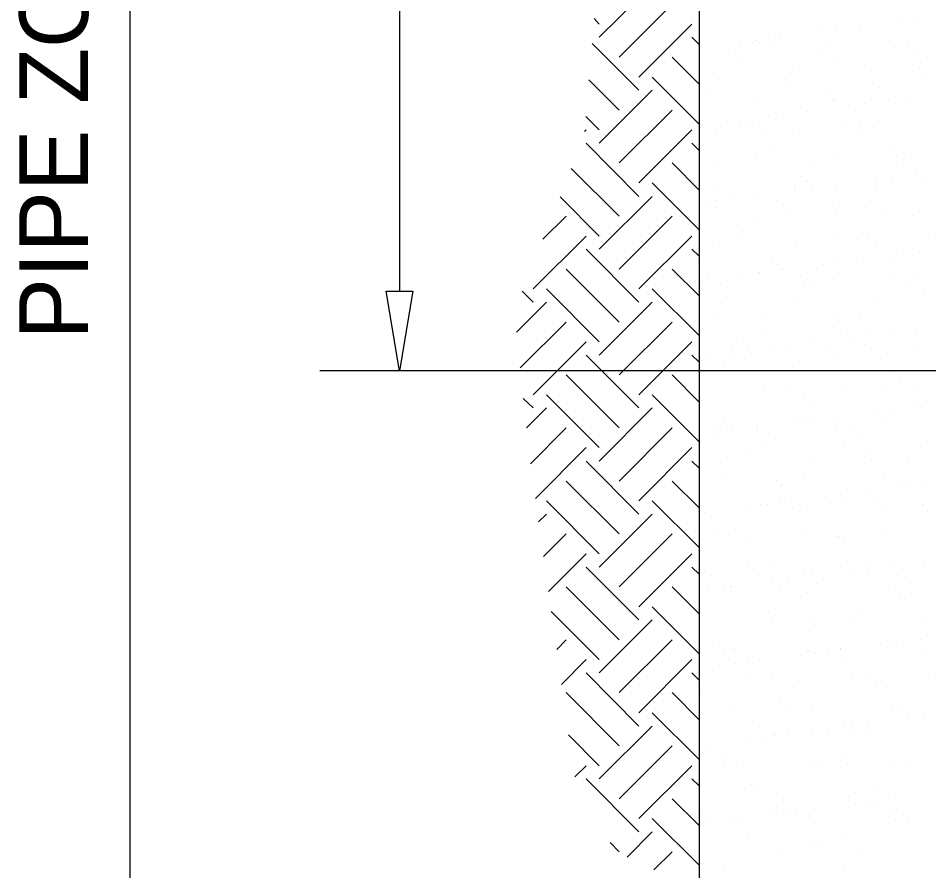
# Model space of a CAD drawing. Extents: x -118779 to -116979, y -104389 to -102939.
# Drawn here: x -117656.9 to -117577.5, y -103296.4 to -103222.1 of the extents above; entities that cross this region are included whole.
import ezdxf

# ---------------------------------------------------------------- set-up
doc = ezdxf.new("R2010")
doc.units = 0
for name, color, linetype in [('G-MARK', 7, 'Continuous'), ('G-TEXT', 7, 'Continuous'), ('Misc CnstDet(22)', 7, 'Continuous')]:
    doc.layers.add(name, color=color, linetype=linetype)

msp = doc.modelspace()

# ---------------------------------------------------------------- linework, layer by layer
at = {"layer": 'G-MARK'}
for p, q in [((-117647.13, -103155.313), (-117647.13, -103305.517)), ((-117623.616, -103155.313), (-117623.616, -103245.874)), ((-117512.18, -103252.832), (-117630.574, -103252.832))]:
    msp.add_line(p, q, dxfattribs=at)
at = {"layer": 'G-TEXT'}
msp.add_lwpolyline([(-117624.781, -103245.874), (-117622.45, -103245.874), (-117623.616, -103252.832)], close=True, dxfattribs=at)
at = {"layer": 'Misc CnstDet(22)'}
for p, q in [((-117597.496, -103148.355), (-117597.496, -103341.508)), ((-117606.203, -103223.731), (-117601.575, -103219.138)), ((-117604.455, -103225.479), (-117599.827, -103220.851)), ((-117606.203, -103222.6), (-117606.648, -103222.12)), ((-117579.809, -103222.325), (-117579.809, -103222.325)), ((-117578.472, -103222.154), (-117578.472, -103222.154)), ((-117602.741, -103227.227), (-117598.113, -103222.6)), ((-117586.836, -103223.251), (-117586.836, -103223.251)), ((-117585.499, -103223.08), (-117585.499, -103223.08)), ((-117583.374, -103222.805), (-117583.374, -103222.805)), ((-117597.496, -103224.382), (-117598.113, -103223.731)), ((-117592.526, -103224.005), (-117592.526, -103224.005)), ((-117591.463, -103223.799), (-117591.463, -103223.799)), ((-117590.401, -103223.731), (-117590.401, -103223.731)), ((-117586.013, -103224.142), (-117586.013, -103224.142)), ((-117580.872, -103224.005), (-117580.872, -103224.005)), ((-117602.741, -103228.358), (-117606.82, -103224.279)), ((-117597.428, -103224.656), (-117597.428, -103224.656)), ((-117594.96, -103224.896), (-117594.96, -103224.896)), ((-117593.897, -103224.176), (-117593.897, -103224.176)), ((-117592.835, -103224.245), (-117592.835, -103224.245)), ((-117590.984, -103224.245), (-117590.984, -103224.245)), ((-117586.802, -103224.862), (-117586.802, -103224.862)), ((-117579.329, -103224.176), (-117579.329, -103224.176)), ((-117578.678, -103224.862), (-117578.678, -103224.862)), ((-117597.496, -103227.844), (-117599.827, -103225.479)), ((-117593.829, -103225.582), (-117593.829, -103225.582)), ((-117585.705, -103225.582), (-117585.705, -103225.582)), ((-117577.581, -103225.547), (-117577.581, -103225.547)), ((-117588.721, -103226.302), (-117588.721, -103226.302)), ((-117578.267, -103226.404), (-117578.267, -103226.404)), ((-117597.496, -103231.306), (-117601.575, -103227.227)), ((-117596.228, -103226.816), (-117596.228, -103226.816)), ((-117589.544, -103226.85), (-117589.544, -103226.85)), ((-117582.483, -103226.61), (-117582.483, -103226.61)), ((-117577.787, -103226.85), (-117577.787, -103226.85)), ((-117604.455, -103230.106), (-117607.094, -103227.467)), ((-117581.729, -103228.084), (-117581.729, -103228.084)), ((-117606.203, -103232.986), (-117601.575, -103228.358)), ((-117596.571, -103228.598), (-117596.571, -103228.598)), ((-117589.887, -103228.118), (-117589.887, -103228.118)), ((-117586.116, -103228.701), (-117586.116, -103228.701)), ((-117592.697, -103229.249), (-117592.697, -103229.249)), ((-117585.842, -103229.181), (-117585.842, -103229.181)), ((-117585.636, -103229.147), (-117585.636, -103229.147)), ((-117584.437, -103229.695), (-117584.437, -103229.695)), ((-117583.1, -103229.524), (-117583.1, -103229.524)), ((-117580.975, -103229.249), (-117580.975, -103229.249)), ((-117579.158, -103229.215), (-117579.158, -103229.215)), ((-117604.455, -103234.7), (-117599.827, -103230.106)), ((-117590.127, -103230.449), (-117590.127, -103230.449)), ((-117588.001, -103230.175), (-117588.001, -103230.175)), ((-117606.203, -103231.82), (-117607.368, -103230.655)), ((-117595.028, -103231.1), (-117595.028, -103231.1)), ((-117593.966, -103230.998), (-117593.966, -103230.998)), ((-117591.463, -103230.621), (-117591.463, -103230.621)), ((-117583.374, -103231.203), (-117583.374, -103231.203)), ((-117607.471, -103231.957), (-117607.334, -103231.82)), ((-117602.741, -103236.448), (-117598.113, -103231.82)), ((-117597.153, -103231.375), (-117597.153, -103231.375)), ((-117596.057, -103231.855), (-117596.057, -103231.855)), ((-117593.486, -103231.443), (-117593.486, -103231.443)), ((-117592.835, -103231.409), (-117592.835, -103231.409)), ((-117589.372, -103231.889), (-117589.372, -103231.889)), ((-117584.711, -103231.409), (-117584.711, -103231.409)), ((-117582.311, -103231.615), (-117582.311, -103231.615)), ((-117591.738, -103232.129), (-117591.738, -103232.129)), ((-117583.614, -103232.129), (-117583.614, -103232.129)), ((-117602.741, -103237.613), (-117607.334, -103232.986)), ((-117597.496, -103233.603), (-117598.113, -103232.986)), ((-117591.223, -103233.5), (-117591.223, -103233.5)), ((-117580.769, -103233.603), (-117580.769, -103233.603)), ((-117592.526, -103234.288), (-117592.526, -103234.288)), ((-117585.671, -103234.22), (-117585.671, -103234.22)), ((-117580.289, -103234.048), (-117580.289, -103234.048)), ((-117578.986, -103234.254), (-117578.986, -103234.254)), ((-117604.455, -103239.327), (-117608.636, -103235.179)), ((-117597.496, -103237.065), (-117599.827, -103234.7)), ((-117595.919, -103234.665), (-117595.919, -103234.665)), ((-117587.761, -103234.665), (-117587.761, -103234.665)), ((-117579.638, -103234.631), (-117579.638, -103234.631)), ((-117588.618, -103235.899), (-117588.618, -103235.899)), ((-117580.666, -103235.968), (-117580.666, -103235.968)), ((-117578.541, -103235.694), (-117578.541, -103235.694)), ((-117597.496, -103240.527), (-117601.575, -103236.448)), ((-117588.139, -103236.345), (-117588.139, -103236.345)), ((-117585.568, -103236.619), (-117585.568, -103236.619)), ((-117582.14, -103236.653), (-117582.14, -103236.653)), ((-117582.037, -103236.139), (-117582.037, -103236.139)), ((-117578.027, -103236.105), (-117578.027, -103236.105)), ((-117606.203, -103242.206), (-117601.575, -103237.613)), ((-117595.885, -103236.893), (-117595.885, -103236.893)), ((-117592.629, -103237.545), (-117592.629, -103237.545)), ((-117589.201, -103236.928), (-117589.201, -103236.928)), ((-117589.064, -103237.065), (-117589.064, -103237.065)), ((-117587.693, -103236.893), (-117587.693, -103236.893)), ((-117606.203, -103241.075), (-117609.596, -103237.647)), ((-117596.468, -103238.196), (-117596.468, -103238.196)), ((-117596.091, -103237.99), (-117596.091, -103237.99)), ((-117594.754, -103237.819), (-117594.754, -103237.819)), ((-117590.709, -103237.956), (-117590.709, -103237.956)), ((-117585.876, -103238.402), (-117585.876, -103238.402)), ((-117582.586, -103237.956), (-117582.586, -103237.956)), ((-117595.988, -103238.607), (-117595.988, -103238.607)), ((-117589.612, -103238.676), (-117589.612, -103238.676)), ((-117581.489, -103238.641), (-117581.489, -103238.641)), ((-117611.104, -103241.349), (-117609.082, -103239.327)), ((-117604.455, -103243.954), (-117599.827, -103239.327)), ((-117592.355, -103239.327), (-117592.355, -103239.327)), ((-117585.533, -103239.258), (-117585.533, -103239.258)), ((-117578.849, -103239.258), (-117578.849, -103239.258)), ((-117593.726, -103240.698), (-117593.726, -103240.698)), ((-117583.271, -103240.801), (-117583.271, -103240.801)), ((-117611.961, -103245.668), (-117607.334, -103241.075)), ((-117602.741, -103245.668), (-117598.113, -103241.075)), ((-117593.794, -103241.212), (-117593.794, -103241.212)), ((-117585.671, -103241.178), (-117585.671, -103241.178)), ((-117582.791, -103241.247), (-117582.791, -103241.247)), ((-117577.513, -103241.178), (-117577.513, -103241.178)), ((-117602.741, -103246.834), (-117607.334, -103242.206)), ((-117597.496, -103242.823), (-117598.113, -103242.206)), ((-117595.714, -103241.898), (-117595.714, -103241.898)), ((-117589.03, -103241.932), (-117589.03, -103241.932)), ((-117582.003, -103241.692), (-117582.003, -103241.692)), ((-117591.121, -103243.098), (-117591.121, -103243.098)), ((-117583.168, -103243.063), (-117583.168, -103243.063)), ((-117579.638, -103242.583), (-117579.638, -103242.583)), ((-117578.267, -103242.412), (-117578.267, -103242.412)), ((-117604.455, -103248.582), (-117609.082, -103243.954)), ((-117597.496, -103246.285), (-117599.827, -103243.954)), ((-117590.641, -103243.543), (-117590.641, -103243.543)), ((-117590.195, -103243.989), (-117590.195, -103243.989)), ((-117586.665, -103243.509), (-117586.665, -103243.509)), ((-117585.293, -103243.337), (-117585.293, -103243.337)), ((-117580.529, -103243.303), (-117580.529, -103243.303)), ((-117596.742, -103244.537), (-117596.742, -103244.537)), ((-117593.691, -103244.434), (-117593.691, -103244.434)), ((-117592.32, -103244.263), (-117592.32, -103244.263)), ((-117592.183, -103244.366), (-117592.183, -103244.366)), ((-117588.618, -103244.503), (-117588.618, -103244.503)), ((-117585.362, -103244.263), (-117585.362, -103244.263)), ((-117580.495, -103244.503), (-117580.495, -103244.503)), ((-117578.678, -103244.297), (-117578.678, -103244.297)), ((-117597.222, -103244.914), (-117597.222, -103244.914)), ((-117595.645, -103245.223), (-117595.645, -103245.223)), ((-117587.522, -103245.223), (-117587.522, -103245.223)), ((-117579.398, -103245.188), (-117579.398, -103245.188)), ((-117611.961, -103246.834), (-117612.921, -103245.874)), ((-117606.203, -103250.296), (-117610.796, -103245.668)), ((-117597.496, -103249.747), (-117601.575, -103245.668)), ((-117588.378, -103245.6), (-117588.378, -103245.6)), ((-117577.924, -103245.703), (-117577.924, -103245.703)), ((-117613.401, -103249.439), (-117610.796, -103246.834)), ((-117606.203, -103251.461), (-117601.575, -103246.834)), ((-117595.577, -103246.937), (-117595.577, -103246.937)), ((-117588.893, -103246.971), (-117588.893, -103246.971)), ((-117581.831, -103246.731), (-117581.831, -103246.731)), ((-117596.228, -103247.896), (-117596.228, -103247.896)), ((-117591.669, -103247.759), (-117591.669, -103247.759)), ((-117583.545, -103247.725), (-117583.545, -103247.725)), ((-117613.092, -103252.558), (-117609.082, -103248.582)), ((-117604.455, -103253.175), (-117599.827, -103248.582)), ((-117585.773, -103247.999), (-117585.773, -103247.999)), ((-117585.293, -103248.445), (-117585.293, -103248.445)), ((-117592.012, -103249.405), (-117592.012, -103249.405)), ((-117585.191, -103249.302), (-117585.191, -103249.302)), ((-117580.769, -103249.507), (-117580.769, -103249.507)), ((-117578.507, -103249.336), (-117578.507, -103249.336)), ((-117611.961, -103254.923), (-117607.334, -103250.296)), ((-117602.741, -103254.923), (-117598.113, -103250.296)), ((-117593.623, -103250.296), (-117593.623, -103250.296)), ((-117584.265, -103249.953), (-117584.265, -103249.953)), ((-117582.894, -103249.782), (-117582.894, -103249.782)), ((-117594.651, -103251.05), (-117594.651, -103251.05)), ((-117593.143, -103250.741), (-117593.143, -103250.741)), ((-117591.292, -103250.879), (-117591.292, -103250.879)), ((-117589.921, -103250.707), (-117589.921, -103250.707)), ((-117587.796, -103250.433), (-117587.796, -103250.433)), ((-117586.493, -103251.05), (-117586.493, -103251.05)), ((-117583.031, -103250.501), (-117583.031, -103250.501)), ((-117578.369, -103251.016), (-117578.369, -103251.016)), ((-117602.741, -103256.054), (-117607.334, -103251.461)), ((-117597.496, -103252.078), (-117598.113, -103251.461)), ((-117596.948, -103251.633), (-117596.948, -103251.633)), ((-117594.823, -103251.358), (-117594.823, -103251.358)), ((-117593.554, -103251.77), (-117593.554, -103251.77)), ((-117585.396, -103251.735), (-117585.396, -103251.735)), ((-117581.66, -103251.77), (-117581.66, -103251.77)), ((-117595.405, -103251.975), (-117595.405, -103251.975)), ((-117588.721, -103252.01), (-117588.721, -103252.01)), ((-117623.616, -103252.832), (-117623.616, -103252.832)), ((-117604.455, -103257.803), (-117609.082, -103253.175)), ((-117597.496, -103255.54), (-117599.827, -103253.175)), ((-117590.881, -103252.798), (-117590.881, -103252.798)), ((-117580.426, -103252.901), (-117580.426, -103252.901)), ((-117579.946, -103253.346), (-117579.946, -103253.346)), ((-117589.578, -103254.306), (-117589.578, -103254.306)), ((-117581.454, -103254.272), (-117581.454, -103254.272)), ((-117606.203, -103259.516), (-117610.796, -103254.923)), ((-117597.496, -103259.002), (-117601.575, -103254.923)), ((-117591.875, -103254.443), (-117591.875, -103254.443)), ((-117585.019, -103254.341), (-117585.019, -103254.341)), ((-117578.335, -103254.375), (-117578.335, -103254.375)), ((-117611.961, -103256.054), (-117612.818, -103255.232)), ((-117588.276, -103255.197), (-117588.276, -103255.197)), ((-117587.796, -103255.643), (-117587.796, -103255.643)), ((-117577.65, -103255.437), (-117577.65, -103255.437)), ((-117612.544, -103257.803), (-117610.796, -103256.054)), ((-117606.203, -103260.682), (-117601.575, -103256.054)), ((-117581.831, -103256.431), (-117581.831, -103256.431)), ((-117580.495, -103256.226), (-117580.495, -103256.226)), ((-117578.369, -103255.952), (-117578.369, -103255.952)), ((-117595.234, -103257.014), (-117595.234, -103257.014)), ((-117588.858, -103257.357), (-117588.858, -103257.357)), ((-117588.55, -103257.048), (-117588.55, -103257.048)), ((-117587.522, -103257.151), (-117587.522, -103257.151)), ((-117585.396, -103256.877), (-117585.396, -103256.877)), ((-117581.489, -103256.774), (-117581.489, -103256.774)), ((-117612.201, -103260.922), (-117609.082, -103257.803)), ((-117604.455, -103262.43), (-117599.827, -103257.803)), ((-117596.125, -103257.494), (-117596.125, -103257.494)), ((-117595.919, -103258.282), (-117595.919, -103258.282)), ((-117595.645, -103257.94), (-117595.645, -103257.94)), ((-117594.548, -103258.077), (-117594.548, -103258.077)), ((-117592.526, -103257.597), (-117592.526, -103257.597)), ((-117592.423, -103257.803), (-117592.423, -103257.803)), ((-117585.499, -103257.7), (-117585.499, -103257.7)), ((-117584.402, -103257.597), (-117584.402, -103257.597)), ((-117583.305, -103258.282), (-117583.305, -103258.282)), ((-117591.429, -103258.317), (-117591.429, -103258.317)), ((-117611.756, -103263.938), (-117607.334, -103259.516)), ((-117602.741, -103264.144), (-117598.113, -103259.516)), ((-117591.703, -103259.448), (-117591.703, -103259.448)), ((-117584.848, -103259.379), (-117584.848, -103259.379)), ((-117578.164, -103259.414), (-117578.164, -103259.414)), ((-117593.349, -103259.996), (-117593.349, -103259.996)), ((-117582.928, -103260.099), (-117582.928, -103260.099)), ((-117582.448, -103260.545), (-117582.448, -103260.545)), ((-117602.741, -103265.309), (-117607.334, -103260.682)), ((-117597.496, -103261.299), (-117598.113, -103260.682)), ((-117595.611, -103260.853), (-117595.611, -103260.853)), ((-117587.453, -103260.819), (-117587.453, -103260.819)), ((-117579.329, -103260.819), (-117579.329, -103260.819)), ((-117595.063, -103262.053), (-117595.063, -103262.053)), ((-117588.378, -103262.087), (-117588.378, -103262.087)), ((-117581.317, -103261.813), (-117581.317, -103261.813)), ((-117604.455, -103267.023), (-117609.082, -103262.43)), ((-117597.496, -103264.761), (-117599.827, -103262.43)), ((-117590.778, -103262.396), (-117590.778, -103262.396)), ((-117590.298, -103262.841), (-117590.298, -103262.841)), ((-117580.152, -103262.636), (-117580.152, -103262.636)), ((-117579.432, -103262.876), (-117579.432, -103262.876)), ((-117578.061, -103262.67), (-117578.061, -103262.67)), ((-117586.459, -103263.801), (-117586.459, -103263.801)), ((-117585.122, -103263.595), (-117585.122, -103263.595)), ((-117582.997, -103263.321), (-117582.997, -103263.321)), ((-117606.203, -103268.771), (-117610.796, -103264.144)), ((-117597.496, -103268.223), (-117601.575, -103264.144)), ((-117592.149, -103264.521), (-117592.149, -103264.521)), ((-117591.532, -103264.487), (-117591.532, -103264.487)), ((-117590.435, -103264.144), (-117590.435, -103264.144)), ((-117590.024, -103264.247), (-117590.024, -103264.247)), ((-117584.711, -103264.418), (-117584.711, -103264.418)), ((-117582.277, -103264.144), (-117582.277, -103264.144)), ((-117578.027, -103264.452), (-117578.027, -103264.452)), ((-117611.481, -103265.995), (-117610.796, -103265.309)), ((-117606.203, -103269.937), (-117601.575, -103265.309)), ((-117597.462, -103264.864), (-117597.462, -103264.864)), ((-117597.051, -103265.172), (-117597.051, -103265.172)), ((-117593.486, -103264.727), (-117593.486, -103264.727)), ((-117589.304, -103264.829), (-117589.304, -103264.829)), ((-117588.001, -103264.898), (-117588.001, -103264.898)), ((-117581.18, -103264.829), (-117581.18, -103264.829)), ((-117577.547, -103265.001), (-117577.547, -103265.001)), ((-117581.18, -103266.852), (-117581.18, -103266.852)), ((-117611.07, -103269.011), (-117609.082, -103267.023)), ((-117604.455, -103271.651), (-117599.827, -103267.023)), ((-117595.851, -103267.195), (-117595.851, -103267.195)), ((-117594.891, -103267.092), (-117594.891, -103267.092)), ((-117593.486, -103267.4), (-117593.486, -103267.4)), ((-117588.207, -103267.126), (-117588.207, -103267.126)), ((-117585.396, -103267.297), (-117585.396, -103267.297)), ((-117585.362, -103267.366), (-117585.362, -103267.366)), ((-117584.916, -103267.743), (-117584.916, -103267.743)), ((-117610.625, -103272.062), (-117607.334, -103268.771)), ((-117602.741, -103273.399), (-117598.113, -103268.771)), ((-117602.741, -103274.53), (-117607.334, -103269.937)), ((-117597.496, -103270.554), (-117598.113, -103269.937)), ((-117593.28, -103269.594), (-117593.28, -103269.594)), ((-117592.766, -103270.04), (-117592.766, -103270.04)), ((-117591.361, -103269.525), (-117591.361, -103269.525)), ((-117584.539, -103269.423), (-117584.539, -103269.423)), ((-117582.688, -103270.04), (-117582.688, -103270.04)), ((-117582.654, -103269.834), (-117582.654, -103269.834)), ((-117580.563, -103269.765), (-117580.563, -103269.765)), ((-117577.855, -103269.457), (-117577.855, -103269.457)), ((-117596.434, -103270.691), (-117596.434, -103270.691)), ((-117589.715, -103270.965), (-117589.715, -103270.965)), ((-117588.31, -103270.691), (-117588.31, -103270.691)), ((-117587.59, -103270.691), (-117587.59, -103270.691)), ((-117584.059, -103270.245), (-117584.059, -103270.245)), ((-117580.186, -103270.657), (-117580.186, -103270.657)), ((-117604.455, -103276.278), (-117609.082, -103271.651)), ((-117597.496, -103274.016), (-117599.827, -103271.651)), ((-117595.337, -103271.411), (-117595.337, -103271.411)), ((-117594.651, -103271.616), (-117594.651, -103271.616)), ((-117591.086, -103271.171), (-117591.086, -103271.171)), ((-117587.213, -103271.376), (-117587.213, -103271.376)), ((-117579.089, -103271.376), (-117579.089, -103271.376)), ((-117596.742, -103271.891), (-117596.742, -103271.891)), ((-117594.754, -103272.096), (-117594.754, -103272.096)), ((-117590.504, -103272.096), (-117590.504, -103272.096)), ((-117588.07, -103272.131), (-117588.07, -103272.131)), ((-117581.009, -103271.891), (-117581.009, -103271.891)), ((-117580.049, -103272.199), (-117580.049, -103272.199)), ((-117579.569, -103272.645), (-117579.569, -103272.645)), ((-117606.203, -103277.992), (-117610.385, -103273.81)), ((-117597.496, -103277.478), (-117601.575, -103273.399)), ((-117591.395, -103273.913), (-117591.395, -103273.913)), ((-117583.237, -103273.913), (-117583.237, -103273.913)), ((-117606.203, -103279.157), (-117601.575, -103274.53)), ((-117591.189, -103274.564), (-117591.189, -103274.564)), ((-117587.899, -103274.496), (-117587.899, -103274.496)), ((-117587.419, -103274.941), (-117587.419, -103274.941)), ((-117584.368, -103274.461), (-117584.368, -103274.461)), ((-117577.684, -103274.496), (-117577.684, -103274.496)), ((-117609.905, -103277.101), (-117609.082, -103276.278)), ((-117604.455, -103280.871), (-117599.827, -103276.278)), ((-117580.289, -103276.484), (-117580.289, -103276.484)), ((-117578.164, -103276.21), (-117578.164, -103276.21)), ((-117595.748, -103276.792), (-117595.748, -103276.792)), ((-117595.268, -103277.238), (-117595.268, -103277.238)), ((-117594.583, -103277.135), (-117594.583, -103277.135)), ((-117594.343, -103277.238), (-117594.343, -103277.238)), ((-117587.899, -103277.169), (-117587.899, -103277.169)), ((-117586.219, -103277.238), (-117586.219, -103277.238)), ((-117585.191, -103277.135), (-117585.191, -103277.135)), ((-117585.156, -103277.032), (-117585.156, -103277.032)), ((-117581.66, -103276.689), (-117581.66, -103276.689)), ((-117580.837, -103276.929), (-117580.837, -103276.929)), ((-117578.061, -103277.204), (-117578.061, -103277.204)), ((-117609.493, -103280.151), (-117607.334, -103277.992)), ((-117602.741, -103282.619), (-117598.113, -103277.992)), ((-117593.246, -103277.923), (-117593.246, -103277.923)), ((-117592.218, -103278.061), (-117592.218, -103278.061)), ((-117588.687, -103277.615), (-117588.687, -103277.615)), ((-117587.316, -103277.409), (-117587.316, -103277.409)), ((-117585.088, -103277.923), (-117585.088, -103277.923)), ((-117595.714, -103278.54), (-117595.714, -103278.54)), ((-117594.343, -103278.335), (-117594.343, -103278.335)), ((-117602.741, -103283.785), (-117607.334, -103279.157)), ((-117597.496, -103279.774), (-117598.113, -103279.157)), ((-117593.006, -103279.295), (-117593.006, -103279.295)), ((-117591.052, -103279.603), (-117591.052, -103279.603)), ((-117584.197, -103279.5), (-117584.197, -103279.5)), ((-117582.551, -103279.397), (-117582.551, -103279.397)), ((-117577.513, -103279.534), (-117577.513, -103279.534)), ((-117597.393, -103280.494), (-117597.393, -103280.494)), ((-117589.27, -103280.46), (-117589.27, -103280.46)), ((-117582.071, -103279.843), (-117582.071, -103279.843)), ((-117581.146, -103280.46), (-117581.146, -103280.46)), ((-117604.455, -103285.499), (-117609.082, -103280.871)), ((-117597.496, -103283.236), (-117599.827, -103280.871)), ((-117590.401, -103281.694), (-117590.401, -103281.694)), ((-117580.666, -103281.968), (-117580.666, -103281.968)), ((-117579.809, -103281.934), (-117579.809, -103281.934)), ((-117597.496, -103286.698), (-117601.575, -103282.619)), ((-117594.411, -103282.174), (-117594.411, -103282.174)), ((-117589.921, -103282.14), (-117589.921, -103282.14)), ((-117587.727, -103282.208), (-117587.727, -103282.208)), ((-117582.791, -103283.579), (-117582.791, -103283.579)), ((-117579.226, -103283.134), (-117579.226, -103283.134)), ((-117577.89, -103282.928), (-117577.89, -103282.928)), ((-117606.203, -103288.378), (-117601.575, -103283.785)), ((-117592.218, -103283.785), (-117592.218, -103283.785)), ((-117591.121, -103284.47), (-117591.121, -103284.47)), ((-117587.659, -103284.23), (-117587.659, -103284.23)), ((-117586.288, -103284.059), (-117586.288, -103284.059)), ((-117584.916, -103283.853), (-117584.916, -103283.853)), ((-117584.094, -103283.751), (-117584.094, -103283.751)), ((-117582.997, -103284.47), (-117582.997, -103284.47)), ((-117606.203, -103287.247), (-117608.876, -103284.539)), ((-117593.314, -103284.985), (-117593.314, -103284.985)), ((-117591.943, -103284.779), (-117591.943, -103284.779)), ((-117590.881, -103284.608), (-117590.881, -103284.608)), ((-117589.818, -103284.505), (-117589.818, -103284.505)), ((-117584.025, -103284.539), (-117584.025, -103284.539)), ((-117604.455, -103290.126), (-117599.827, -103285.499)), ((-117596.845, -103285.43), (-117596.845, -103285.43)), ((-117595.508, -103286.493), (-117595.508, -103286.493)), ((-117585.054, -103286.596), (-117585.054, -103286.596)), ((-117608.328, -103288.207), (-117607.334, -103287.247)), ((-117602.741, -103291.84), (-117598.113, -103287.247)), ((-117595.302, -103287.007), (-117595.302, -103287.007)), ((-117594.24, -103287.213), (-117594.24, -103287.213)), ((-117587.556, -103287.247), (-117587.556, -103287.247)), ((-117587.144, -103287.007), (-117587.144, -103287.007)), ((-117584.574, -103287.041), (-117584.574, -103287.041)), ((-117580.495, -103286.973), (-117580.495, -103286.973)), ((-117579.021, -103287.007), (-117579.021, -103287.007)), ((-117602.741, -103293.005), (-117607.334, -103288.378)), ((-117597.496, -103288.995), (-117598.113, -103288.378)), ((-117592.903, -103288.892), (-117592.903, -103288.892)), ((-117582.311, -103289.132), (-117582.311, -103289.132)), ((-117592.423, -103289.338), (-117592.423, -103289.338)), ((-117590.709, -103289.646), (-117590.709, -103289.646)), ((-117583.888, -103289.578), (-117583.888, -103289.578)), ((-117580.392, -103290.023), (-117580.392, -103290.023)), ((-117597.496, -103292.457), (-117599.827, -103290.126)), ((-117590.127, -103290.332), (-117590.127, -103290.332)), ((-117583.854, -103290.503), (-117583.854, -103290.503)), ((-117582.517, -103290.332), (-117582.517, -103290.332)), ((-117581.969, -103290.298), (-117581.969, -103290.298)), ((-117597.153, -103291.052), (-117597.153, -103291.052)), ((-117590.881, -103291.429), (-117590.881, -103291.429)), ((-117590.161, -103291.429), (-117590.161, -103291.429)), ((-117589.544, -103291.257), (-117589.544, -103291.257)), ((-117589.03, -103291.017), (-117589.03, -103291.017)), ((-117587.419, -103290.949), (-117587.419, -103290.949)), ((-117580.872, -103291.017), (-117580.872, -103291.017)), ((-117579.706, -103291.497), (-117579.706, -103291.497)), ((-117597.496, -103295.919), (-117601.575, -103291.84)), ((-117596.571, -103292.183), (-117596.571, -103292.183)), ((-117594.446, -103291.874), (-117594.446, -103291.874)), ((-117594.069, -103292.251), (-117594.069, -103292.251)), ((-117587.384, -103292.286), (-117587.384, -103292.286)), ((-117580.358, -103292.011), (-117580.358, -103292.011)), ((-117579.226, -103291.943), (-117579.226, -103291.943)), ((-117603.769, -103295.199), (-117601.575, -103293.005)), ((-117604.455, -103294.754), (-117605.243, -103293.931)), ((-117593.177, -103293.554), (-117593.177, -103293.554)), ((-117587.556, -103293.794), (-117587.556, -103293.794)), ((-117585.054, -103293.554), (-117585.054, -103293.554)), ((-117601.438, -103296.33), (-117599.827, -103294.754)), ((-117590.538, -103294.685), (-117590.538, -103294.685)), ((-117587.076, -103294.239), (-117587.076, -103294.239)), ((-117583.717, -103294.617), (-117583.717, -103294.617)), ((-117595.405, -103296.09), (-117595.405, -103296.09)), ((-117584.814, -103296.33), (-117584.814, -103296.33))]:
    msp.add_line(p, q, dxfattribs=at)

# ---------------------------------------------------------------- texts
msp.add_text('PIPE ZONE', height=6, rotation=90, dxfattribs=at).set_placement((-117650.774, -103250.083))

doc.saveas('drawing.dxf')
